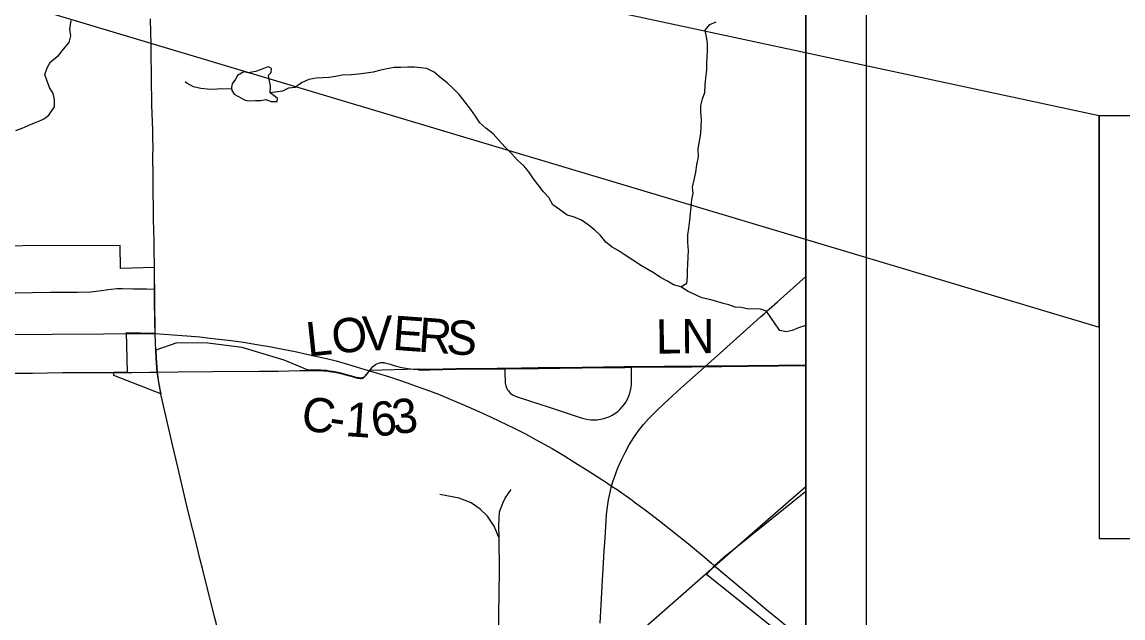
# Model space of a CAD drawing. Extents: x 0 to 34, y 0 to 22.
# Drawn here: x 7.601 to 9.426, y 15.476 to 16.463 of the extents above; entities that cross this region are included whole.
import ezdxf

# ---------------------------------------------------------------- set-up
doc = ezdxf.new("R2010")
doc.units = 0
for name, color, linetype in [('GM_X_City_Street', 7, 'Continuous'), ('GM_X_Corporation', 7, 'Continuous'), ('GM_X_County_Road', 7, 'Continuous'), ('GM_X_County_Road_Text', 7, 'Continuous'), ('GM_X_Minor_Lake', 7, 'Continuous'), ('GM_X_Minor_River', 7, 'Continuous'), ('GM_X_Rail_Line', 7, 'Continuous'), ('GM_X_State_Route', 7, 'Continuous'), ('SH_Data', 7, 'Continuous'), ('SH_Text', 7, 'Continuous')]:
    doc.layers.add(name, color=color, linetype=linetype)

msp = doc.modelspace()

# ---------------------------------------------------------------- linework, layer by layer
at = {"layer": 'GM_X_City_Street'}
for points in [[(7.5403, 16.0143), (7.5913, 16.0146), (7.6186, 16.0151), (7.6484, 16.0157), (7.6776, 16.0158), (7.6931, 16.0158), (7.7155, 16.0163), (7.7241, 16.0171), (7.7493, 16.0208), (7.7586, 16.0216), (7.7679, 16.0219), (7.7856, 16.0214), (7.8082, 16.0209), (7.821, 16.0207)], [(8.4014, 15.8888), (8.4015, 15.8795), (8.4018, 15.8698), (8.4022, 15.8648), (8.4026, 15.8624), (8.403, 15.8606), (8.4036, 15.8586), (8.4047, 15.8562), (8.406, 15.8539), (8.4073, 15.852), (8.4085, 15.8504), (8.4104, 15.8484), (8.4121, 15.847), (8.4141, 15.8455), (8.4165, 15.8442), (8.4238, 15.8416), (8.4749, 15.8251), (8.5279, 15.8077), (8.5345, 15.8059), (8.5393, 15.8049), (8.5441, 15.8043), (8.5496, 15.8041), (8.5545, 15.8043), (8.56, 15.8051), (8.5654, 15.8064), (8.5706, 15.808), (8.5752, 15.8099), (8.5795, 15.8121), (8.5837, 15.8147), (8.5891, 15.8187), (8.5923, 15.8215), (8.5961, 15.8255), (8.5991, 15.8294), (8.6018, 15.8335), (8.6045, 15.8383), (8.607, 15.8439), (8.6086, 15.8485), (8.6097, 15.8527), (8.6106, 15.8575), (8.6112, 15.8636), (8.6114, 15.8678), (8.6114, 15.8716), (8.6114, 15.8828), (8.6116, 15.8912)]]:
    msp.add_lwpolyline(points, dxfattribs=at)
at = {"layer": 'GM_X_Corporation'}
for points in [[(5.0398, 14.1), (8.9, 14.1), (8.9, 17.5277)], [(8.9, 15.416), (8.7354, 15.548), (8.7491, 15.5626), (8.7644, 15.5769), (8.9, 15.6862), (8.9, 15.8946), (8.8553, 15.8941), (8.8039, 15.8936), (8.7611, 15.8932), (8.7334, 15.8929), (8.7105, 15.8927), (8.6658, 15.8923), (8.6114, 15.8918), (8.5999, 15.8917), (8.5294, 15.891), (8.4569, 15.89), (8.4012, 15.8893), (8.3885, 15.8892), (8.3208, 15.8886), (8.2771, 15.8874), (8.2676, 15.8876), (8.259, 15.8878), (8.2585, 15.8878), (8.1771, 15.8859), (8.1717, 15.879), (8.1695, 15.8766), (8.1678, 15.8749), (8.167, 15.8744), (8.1661, 15.8739), (8.1651, 15.8735), (8.164, 15.8733), (8.163, 15.8732), (8.162, 15.8733), (8.16, 15.8735), (8.1576, 15.8739), (8.1533, 15.8749), (8.1481, 15.8763), (8.1397, 15.8786), (8.1298, 15.8813), (8.1246, 15.8825), (8.1199, 15.8835), (8.1152, 15.8843), (8.1107, 15.885), (8.1061, 15.8856), (8.1009, 15.8861), (8.0964, 15.8864), (8.0908, 15.8866), (8.0841, 15.8867), (8.0758, 15.8865), (8.036, 15.9028), (7.9662, 15.9242), (7.9093, 15.9313), (7.858, 15.9316), (7.823, 15.9194), (7.8236, 15.9061), (7.8254, 15.8836), (7.8273, 15.8701), (7.8299, 15.8547), (7.8315, 15.8472), (7.7534, 15.8776), (7.7534, 15.8832), (7.7761, 15.8833), (7.7743, 15.9489), (7.8218, 15.9476), (7.8207, 16.0566), (7.7645, 16.0549), (7.7643, 16.0928), (7.4402, 16.0917)]]:
    msp.add_lwpolyline(points, dxfattribs=at)
at = {"layer": 'GM_X_County_Road'}
for p, q in [((8.8907, 15.8939), (8.9, 15.894)), ((7.7535, 15.8827), (7.7763, 15.8828)), ((7.9009, 15.5559), (7.8962, 15.5747)), ((7.9204, 15.4781), (7.9009, 15.5559))]:
    msp.add_line(p, q, dxfattribs=at)
for points in [[(7.8232, 15.9189), (7.8225, 15.9325), (7.822, 15.947)], [(7.8256, 15.883), (7.8238, 15.9055), (7.8232, 15.9189)], [(8.1773, 15.8854), (8.181, 15.8902), (8.1829, 15.8923), (8.1849, 15.8943), (8.1871, 15.8958), (8.1894, 15.8971), (8.192, 15.898), (8.1942, 15.8986), (8.1961, 15.899), (8.1974, 15.8991), (8.1989, 15.8992), (8.2008, 15.899), (8.2026, 15.8985), (8.2113, 15.8961), (8.2199, 15.8935), (8.2309, 15.8907), (8.2406, 15.8889), (8.2503, 15.8878), (8.2578, 15.8873)], [(8.4014, 15.8888), (8.4571, 15.8894), (8.5296, 15.8905), (8.6001, 15.8911), (8.6116, 15.8912)], [(8.6116, 15.8912), (8.666, 15.8918), (8.7107, 15.8921), (8.7336, 15.8924)], [(8.7336, 15.8924), (8.7613, 15.8926), (8.8041, 15.893), (8.8555, 15.8936), (8.8907, 15.8939)], [(7.5584, 15.8811), (7.5729, 15.8812), (7.6187, 15.8817), (7.6683, 15.8823), (7.7451, 15.8827), (7.7535, 15.8827)], [(7.7763, 15.8828), (7.7832, 15.8828), (7.8131, 15.8829), (7.8256, 15.883)], [(7.8256, 15.883), (7.8597, 15.8834), (7.9176, 15.8842), (7.9944, 15.8847), (8.026, 15.885), (8.0618, 15.8857), (8.075, 15.8859)], [(7.8315, 15.8476), (7.8301, 15.8541), (7.8275, 15.8695), (7.8256, 15.883)], [(8.075, 15.8859), (8.076, 15.8859), (8.0843, 15.8861), (8.091, 15.8861), (8.0966, 15.8858), (8.1011, 15.8855), (8.1063, 15.8851), (8.1109, 15.8844), (8.1154, 15.8837), (8.1201, 15.8829), (8.1248, 15.882), (8.13, 15.8807), (8.1399, 15.878), (8.1483, 15.8758), (8.1535, 15.8743), (8.1578, 15.8734), (8.1602, 15.8729), (8.1622, 15.8727), (8.1632, 15.8727), (8.1642, 15.8727), (8.1653, 15.8729), (8.1663, 15.8733), (8.1672, 15.8738), (8.168, 15.8744), (8.1697, 15.876), (8.1719, 15.8784), (8.1773, 15.8854)], [(8.2578, 15.8873), (8.2587, 15.8872), (8.2678, 15.887), (8.2773, 15.8869), (8.321, 15.8881), (8.3887, 15.8887), (8.4014, 15.8888)], [(7.8962, 15.5747), (7.8887, 15.6047), (7.8842, 15.6222), (7.8761, 15.6548), (7.8594, 15.7256), (7.8515, 15.7608), (7.8446, 15.7892), (7.8317, 15.8467), (7.8315, 15.8476)], [(7.9403, 15.399), (7.9309, 15.4362), (7.9231, 15.4677), (7.9204, 15.4781)]]:
    msp.add_lwpolyline(points, dxfattribs=at)
at = {"layer": 'GM_X_Minor_Lake'}
msp.add_line((7.953, 16.3433), (7.9712, 16.3337), dxfattribs=at)
msp.add_lwpolyline([(7.9712, 16.3337), (7.9777, 16.3326), (7.9883, 16.3328), (7.997, 16.3332), (8.0053, 16.3349), (8.0145, 16.3312), (8.0243, 16.3313), (8.025, 16.3366), (8.0216, 16.3392), (8.0124, 16.3459), (8.013, 16.3573), (8.0114, 16.3649), (8.0098, 16.3751), (8.0143, 16.3794), (8.0146, 16.3858), (8.0096, 16.3888), (8.0059, 16.3876), (7.9976, 16.3845), (7.9881, 16.3813), (7.9764, 16.3789), (7.9688, 16.3804), (7.9583, 16.3742), (7.9553, 16.3684), (7.9497, 16.3608), (7.9483, 16.3551), (7.9491, 16.3494), (7.953, 16.3433)], dxfattribs=at)
at = {"layer": 'GM_X_Minor_River'}
for points in [[(7.6389, 16.3033), (7.6459, 16.309), (7.6551, 16.3224), (7.655, 16.3346), (7.653, 16.3444), (7.6468, 16.3546), (7.6429, 16.3652), (7.6394, 16.3761), (7.643, 16.3872), (7.6486, 16.3971), (7.6617, 16.4075), (7.6703, 16.4179), (7.6793, 16.429), (7.6822, 16.44), (7.6806, 16.4514), (7.6827, 16.4655)], [(8.6932, 16.0244), (8.703, 16.0306), (8.7044, 16.0408), (8.7043, 16.0511), (8.7049, 16.0621), (8.7055, 16.0735), (8.7058, 16.0845), (8.7045, 16.0978), (8.7047, 16.1107), (8.7061, 16.1217), (8.7079, 16.1346), (8.7093, 16.1464), (8.7103, 16.1563), (8.7116, 16.1692), (8.7134, 16.1791), (8.7122, 16.1894), (8.7154, 16.2015), (8.718, 16.2141), (8.7197, 16.2266), (8.7222, 16.24), (8.7221, 16.2529), (8.7263, 16.2784), (8.7269, 16.2898), (8.7272, 16.3011), (8.7263, 16.3144), (8.7262, 16.3247), (8.7291, 16.3361), (8.7327, 16.3464), (8.7337, 16.3589), (8.7343, 16.3707), (8.7361, 16.384), (8.7363, 16.395), (8.7366, 16.4045), (8.7372, 16.4167), (8.7375, 16.4273), (8.7358, 16.4387), (8.7334, 16.4496), (8.7409, 16.4592), (8.7519, 16.4631)], [(8.241, 16.3885), (8.2289, 16.3876), (8.2179, 16.3878), (8.2062, 16.3854), (8.196, 16.3834), (8.1832, 16.3802), (8.1715, 16.3785), (8.159, 16.3769), (8.1469, 16.3756), (8.1317, 16.375), (8.1208, 16.373), (8.1106, 16.371), (8.0992, 16.3705), (8.0886, 16.37), (8.0765, 16.3676), (8.0645, 16.3621), (8.054, 16.3548), (8.043, 16.3535), (8.0328, 16.3488), (8.0124, 16.3459)], [(8.9, 15.9608), (8.8985, 15.96), (8.8883, 15.9568), (8.8777, 15.9521), (8.8675, 15.9497), (8.8573, 15.9519), (8.8507, 15.9617), (8.8423, 15.9737), (8.8349, 15.9843), (8.8251, 15.9872), (8.8156, 15.9878), (8.805, 15.9877), (8.7932, 15.9902), (8.7834, 15.9909), (8.7727, 15.9946), (8.7632, 15.9967), (8.7511, 16.0008), (8.7404, 16.0033), (8.7279, 16.0062), (8.7172, 16.0114), (8.7054, 16.0166), (8.6932, 16.0244), (8.6807, 16.028), (8.6708, 16.0336), (8.6593, 16.0399), (8.6487, 16.047), (8.6384, 16.053), (8.6277, 16.0593), (8.5991, 16.078), (8.5891, 16.0847), (8.5796, 16.0899), (8.5689, 16.0985), (8.5601, 16.1094), (8.5501, 16.1188), (8.5394, 16.1274), (8.5284, 16.1348), (8.5154, 16.1404), (8.5048, 16.1433), (8.4918, 16.1526), (8.4811, 16.1601), (8.4742, 16.1722), (8.4657, 16.1819), (8.4569, 16.1936), (8.4492, 16.2034), (8.4415, 16.2151), (8.433, 16.2248), (8.4223, 16.2342), (8.4123, 16.2451), (8.402, 16.2556), (8.3905, 16.2684), (8.382, 16.2781), (8.3698, 16.2871), (8.3603, 16.2961), (8.3529, 16.307), (8.3449, 16.3179), (8.336, 16.3304), (8.326, 16.3428), (8.3153, 16.3537), (8.3057, 16.3623), (8.2958, 16.3701), (8.2843, 16.3802), (8.2721, 16.3858), (8.2619, 16.3872), (8.252, 16.3882), (8.241, 16.3885)], [(7.9487, 16.3518), (7.9305, 16.3522), (7.9195, 16.3513), (7.9082, 16.3516), (7.8976, 16.353), (7.8858, 16.3559), (7.8747, 16.3618), (7.8717, 16.364)], [(7.591, 16.2833), (7.6016, 16.2875), (7.6114, 16.2914), (7.6219, 16.296), (7.6333, 16.3006), (7.6389, 16.3033)]]:
    msp.add_lwpolyline(points, dxfattribs=at)
at = {"layer": 'GM_X_Rail_Line'}
for points in [[(8.5472, 15.3849), (8.5748, 15.4092), (8.6353, 15.4621), (8.6975, 15.5165), (8.7491, 15.5615), (8.8375, 15.6391), (8.9, 15.6939)], [(8.392, 15.6079), (8.3839, 15.6278), (8.3729, 15.6447), (8.3608, 15.656), (8.3458, 15.6666), (8.3256, 15.6744), (8.2935, 15.6806)], [(8.392, 15.6079), (8.3917, 15.6298), (8.3929, 15.6517), (8.3979, 15.6662), (8.4022, 15.6744), (8.4117, 15.6886)], [(8.3449, 15.2078), (8.3704, 15.237), (8.3836, 15.2554), (8.3882, 15.2703), (8.3885, 15.301), (8.3928, 15.5534), (8.392, 15.6079)]]:
    msp.add_lwpolyline(points, dxfattribs=at)
at = {"layer": 'GM_X_State_Route'}
msp.add_line((8.744, 15.5665), (8.7493, 15.562), dxfattribs=at)
for points in [[(7.8205, 16.0834), (7.8204, 16.0884), (7.8203, 16.0983), (7.8197, 16.1206), (7.8193, 16.1336), (7.8192, 16.1435), (7.8191, 16.1541), (7.819, 16.1821), (7.8185, 16.2059), (7.8185, 16.2216), (7.8184, 16.2266), (7.8183, 16.2322), (7.8183, 16.2402), (7.8185, 16.2564), (7.8184, 16.2694), (7.818, 16.2842), (7.8167, 16.3256), (7.8164, 16.3393), (7.8161, 16.3579), (7.816, 16.3722), (7.8153, 16.4131), (7.8152, 16.4274), (7.8147, 16.4448), (7.8143, 16.4683)], [(7.8209, 16.0561), (7.8209, 16.0623), (7.8205, 16.0834)], [(7.822, 15.947), (7.8215, 15.9662), (7.8214, 15.976), (7.821, 15.9954), (7.821, 16.0207), (7.821, 16.0246), (7.8209, 16.0377), (7.8209, 16.0561)], [(8.7336, 15.8924), (8.764, 15.9196), (8.8079, 15.9591), (8.8254, 15.9748), (8.8315, 15.9802), (8.837, 15.9851), (8.8397, 15.9876), (8.8532, 15.9996), (8.9, 16.0414)], [(7.822, 15.947), (7.8518, 15.9452), (7.8747, 15.9434), (7.8959, 15.9414), (7.9178, 15.9389), (7.9324, 15.9372), (7.9481, 15.9353), (7.9685, 15.9326), (7.9906, 15.9291), (8.0145, 15.9248), (8.0361, 15.9208), (8.0542, 15.9171), (8.0733, 15.913), (8.0903, 15.9092), (8.106, 15.9055), (8.122, 15.9016), (8.1367, 15.8975), (8.1773, 15.8854)], [(8.653, 15.8189), (8.6651, 15.8308), (8.6936, 15.8573), (8.727, 15.8866), (8.7336, 15.8924)], [(8.1773, 15.8854), (8.1977, 15.8792), (8.2104, 15.8751), (8.2252, 15.8702), (8.2395, 15.8654), (8.2545, 15.8601), (8.2704, 15.8543), (8.2913, 15.8464), (8.3107, 15.8386), (8.3316, 15.8296), (8.3584, 15.8179), (8.3776, 15.8091), (8.3928, 15.802), (8.4158, 15.7908), (8.4357, 15.7807), (8.4532, 15.7712), (8.4798, 15.7564), (8.499, 15.7451), (8.5177, 15.7337), (8.5424, 15.718), (8.57, 15.7001), (8.5785, 15.6945)], [(8.5785, 15.6945), (8.5805, 15.7015), (8.5826, 15.7078), (8.5889, 15.7245), (8.5948, 15.7381), (8.6008, 15.7503), (8.6077, 15.7627), (8.6152, 15.7747), (8.6225, 15.7853), (8.6313, 15.7964), (8.6395, 15.8057), (8.653, 15.8189)], [(8.5662, 15.5866), (8.5675, 15.6086), (8.5701, 15.647), (8.571, 15.6562), (8.572, 15.664), (8.5733, 15.6714), (8.5747, 15.6789), (8.5764, 15.6866), (8.5785, 15.6945)], [(8.5785, 15.6945), (8.5874, 15.6888), (8.6124, 15.671), (8.6164, 15.668)], [(8.6164, 15.668), (8.634, 15.655), (8.6577, 15.6368), (8.6899, 15.6114), (8.706, 15.5986), (8.729, 15.5792), (8.744, 15.5665)], [(8.5592, 15.4672), (8.5628, 15.5286), (8.5662, 15.5866)], [(8.7493, 15.562), (8.7759, 15.5399), (8.8029, 15.5171), (8.8251, 15.4982), (8.8356, 15.4894), (8.8559, 15.473), (8.8693, 15.4617), (8.9, 15.4358)]]:
    msp.add_lwpolyline(points, dxfattribs=at)
at = {"layer": 'SH_Data'}
for p, q in [((9, 21), (9, 14)), ((8.9, 20.9), (8.9, 14.1))]:
    msp.add_line(p, q, dxfattribs=at)
at = {"layer": 'SH_Text'}
for points in [[(9.3865, 16.3077), (5.2632, 17.1919), (9.3865, 15.9577)], [(9.3865, 15.6077), (11.1242, 15.6077), (11.1242, 16.3077), (9.3865, 16.3077)]]:
    msp.add_lwpolyline(points, close=True, dxfattribs=at)
msp.add_lwpolyline([(6.0436, 16.4561), (6.1622, 16.3439), (6.2259, 16.279), (6.2997, 16.2029), (6.3775, 16.1225), (6.4588, 16.0391), (6.4804, 16.0186), (6.5205, 15.9884), (6.5845, 15.9575), (6.6499, 15.9422), (6.7146, 15.9393), (6.7966, 15.9403), (7.822, 15.947)], dxfattribs=at)

# ---------------------------------------------------------------- texts
at = {"layer": 'GM_X_County_Road_Text'}
for s, height, rotation, p in [('L', 0.0568, 6.1187, (8.0752, 15.9087)), ('O', 0.0568, 6.0876, (8.1174, 15.9132)), ('V', 0.0568, 2.1169, (8.1661, 15.9185)), ('E', 0.0568, 355.8478, (8.2144, 15.9203)), ('R', 0.0568, 355.777, (8.2568, 15.9173)), ('S', 0.0568, 355.7816, (8.3033, 15.9138)), ('LN', 0.05682, 0.5134, (8.6519, 15.9138)), ('C', 0.0568, 351.5862, (8.0619, 15.788)), ('6', 0.0568, 7.6538, (8.1834, 15.7753)), ('3', 0.0568, 6.8281, (8.2179, 15.78)), ('1', 0.0568, 356.0186, (8.136, 15.7774)), ('-', 0.0568, 351.8008, (8.1083, 15.7812))]:
    msp.add_text(s, height=height, rotation=rotation, dxfattribs=at).set_placement(p)

doc.saveas('drawing.dxf')
